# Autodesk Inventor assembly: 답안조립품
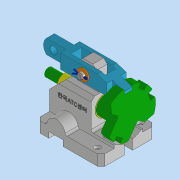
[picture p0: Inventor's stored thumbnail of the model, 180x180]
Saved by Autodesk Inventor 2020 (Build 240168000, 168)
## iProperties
Created: 2022-08
Part Number: 답안조립품
Document SubType Name: Assembly
Designer: MIRAE
Author: MIRAE
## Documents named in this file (8)
- C:\Users\MIRAE\Desktop\720806V1014\답안조립품.iam
- C:\Users\MIRAE\Desktop\720806V1014\본체.ipt
- C:\Users\MIRAE\Desktop\720806V1014\부시.ipt
- C:\Users\MIRAE\Desktop\720806V1014\분할축.ipt
- C:\Users\MIRAE\Desktop\720806V1014\분할대.ipt
- C:\Users\MIRAE\Desktop\720806V1014\클레비스핀.ipt
- C:\Users\MIRAE\Desktop\720806V1014\와셔.ipt
- C:\Users\MIRAE\Desktop\720806V1014\분할핀.ipt
